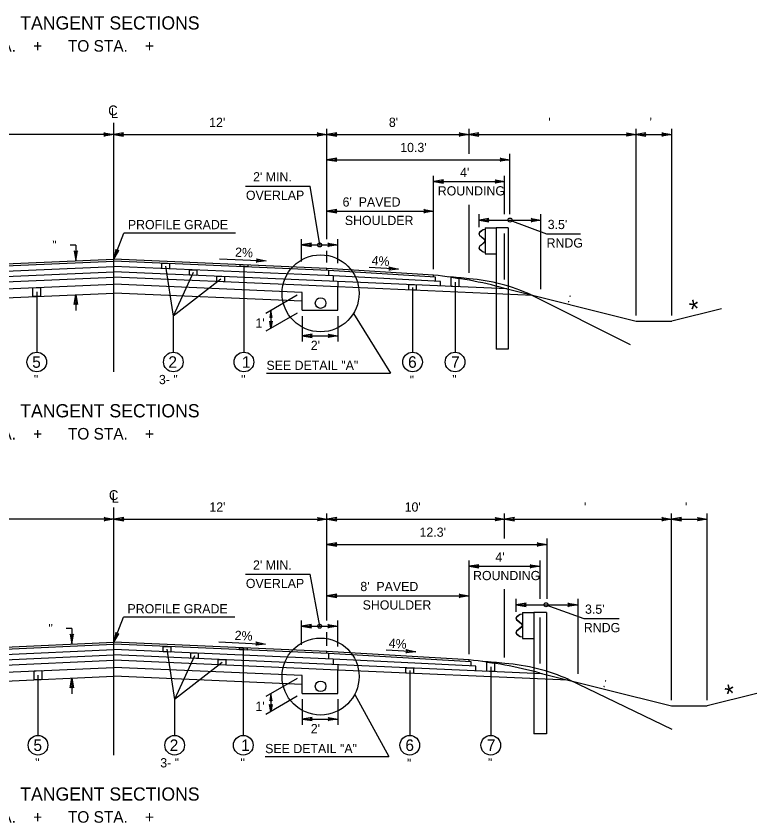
# Model space of a CAD drawing. Extents: x -592 to 1199, y -590 to 416.
# Drawn here: x 227.3 to 339.6, y 43.7 to 166.1 of the extents above; entities that cross this region are included whole.
import ezdxf

# ---------------------------------------------------------------- set-up
doc = ezdxf.new("R2010")
doc.units = 0
doc.layers.add('1', color=7, linetype='Continuous')
doc.layers.add('Des_ Drain_ Ftrs', color=7, linetype='Continuous')

msp = doc.modelspace()

# ---------------------------------------------------------------- linework, layer by layer
at = {"layer": '1'}
for p, q in [((242.09, 112.15), (242.09, 149.92)), ((242.09, 148.16), (209.76, 148.16)), ((242.09, 148.16), (274.42, 148.16)), ((274.42, 132.28), (274.42, 149.04)), ((274.42, 148.16), (295.97, 148.16)), ((295.97, 145.22), (295.97, 149.04)), ((295.97, 148.16), (321.31, 148.16)), ((321.31, 120.71), (321.31, 149.04)), ((321.31, 148.16), (326.69, 148.16)), ((326.69, 120.71), (326.69, 149.04)), ((302.17, 136.06), (302.17, 145.22)), ((274.42, 144.34), (302.17, 144.34)), ((290.58, 127.71), (290.58, 141.89)), ((290.61, 141.01), (301.39, 141.01)), ((301.36, 136.06), (301.36, 141.89)), ((262.09, 140.34), (271.86, 140.34)), ((273.32, 131.4), (271.86, 140.34)), ((295.97, 127.15), (295.97, 137.47)), ((274.42, 136.52), (290.58, 136.52)), ((297.48, 134.11), (297.48, 136.06)), ((306.86, 124.7), (306.86, 136.06)), ((297.48, 135.18), (306.86, 135.18)), ((302.17, 135.18), (307.73, 133.11)), ((298.08, 133.71), (297.56, 133.32)), ((298.09, 133.68), (297.58, 133.3)), ((298.39, 133.77), (298.08, 133.71)), ((298.39, 133.74), (298.09, 133.68)), ((298.39, 134), (298.39, 130.06)), ((298.39, 134), (300.08, 134)), ((300.08, 134), (300.08, 115.6)), ((301.9, 134), (300.08, 134)), ((301.9, 134), (301.9, 115.6)), ((242.09, 129.25), (243.61, 133.21)), ((260.53, 133.21), (243.61, 133.21)), ((270.58, 128.89), (270.58, 132.28)), ((276.06, 128.62), (276.06, 132.28)), ((297.54, 132.89), (298.28, 132.26)), ((297.56, 132.91), (298.3, 132.28)), ((301.36, 126.18), (301.36, 133.14)), ((307.73, 133.11), (312.88, 133.11)), ((236.34, 131.37), (235.46, 131.37)), ((236.34, 131.37), (236.34, 129)), ((270.58, 131.4), (276.06, 131.4)), ((298.28, 131.8), (297.54, 131.17)), ((298.3, 131.78), (297.56, 131.15)), ((298.36, 132.07), (298.36, 131.99)), ((298.39, 132.07), (298.39, 131.99)), ((274.42, 128.72), (274.42, 130.52)), ((297.56, 130.74), (298.08, 130.35)), ((297.58, 130.76), (298.09, 130.38)), ((298.08, 130.35), (298.39, 130.29)), ((298.09, 130.38), (298.39, 130.32)), ((298.39, 130.06), (300.08, 130.06)), ((209.52, 127.53), (242.09, 128.95)), ((209.76, 127.84), (242.09, 129.25)), ((274.42, 127.84), (242.09, 129.25)), ((274.66, 127.53), (242.09, 128.95)), ((258.1, 129.31), (265.19, 129)), ((182.49, 124.73), (242.09, 127.33)), ((208.82, 126.69), (242.09, 128.14)), ((275.37, 126.69), (242.09, 128.14)), ((301.7, 124.73), (242.09, 127.33)), ((249.95, 128.2), (251.12, 120.58)), ((261.83, 128.23), (261.83, 115.12)), ((274.42, 127.54), (274.42, 127.84)), ((290.58, 126.83), (274.42, 127.84)), ((274.66, 127.53), (274.66, 126.72)), ((290.89, 126.51), (274.66, 127.53)), ((285.29, 127.72), (280.8, 127.99)), ((213.6, 125.28), (242.09, 126.53)), ((270.58, 125.28), (242.09, 126.53)), ((254.13, 127.22), (251.12, 120.58)), ((258.3, 126.21), (251.12, 120.58)), ((275.36, 126.69), (275.36, 125.88)), ((291.61, 125.86), (275.36, 126.69)), ((290.58, 126.53), (290.58, 126.83)), ((290.89, 125.9), (290.89, 126.51)), ((213.5, 124.2), (242.09, 125.45)), ((270.68, 124.2), (242.09, 125.45)), ((276.07, 125.04), (270.58, 125.28)), ((276.07, 125.85), (276.07, 125.04)), ((276.07, 121.5), (276.07, 125.04)), ((305.62, 123.75), (276.07, 125.04)), ((287.39, 124.95), (287.39, 115.12)), ((291.61, 125.17), (291.61, 125.86)), ((293.84, 125.77), (293.84, 115.12)), ((297.48, 126.05), (297.48, 126.05)), ((213.5, 122.85), (242.09, 124.1)), ((230.41, 124.27), (230.41, 115.12)), ((236.34, 123.85), (236.34, 121.48)), ((270.68, 122.85), (242.09, 124.1)), ((269.92, 123.76), (265.16, 121.01)), ((270.68, 121.5), (270.68, 124.2)), ((270.68, 124.2), (270.68, 124.2)), ((301.36, 124.82), (321.31, 119.83)), ((305.36, 123.82), (320.41, 116.29)), ((265.92, 121.45), (265.9, 118.75)), ((270.68, 121.5), (276.07, 121.5)), ((334.23, 121.71), (326.69, 119.83)), ((334.23, 121.71), (326.69, 119.83)), ((251.12, 120.58), (251.12, 115.12)), ((269.92, 121.06), (265.14, 118.31)), ((270.68, 120.62), (270.68, 116.74)), ((276.07, 120.62), (276.07, 116.74)), ((278.44, 121.02), (284.03, 111.94)), ((321.31, 119.83), (326.69, 119.83)), ((270.68, 117.62), (276.07, 117.62)), ((301.9, 115.6), (300.08, 115.6)), ((265.24, 111.94), (284.03, 111.94)), ((242.09, 54.01), (242.09, 91.55)), ((274.42, 74.43), (274.42, 90.67)), ((301.36, 86.85), (301.36, 90.67)), ((326.68, 62.33), (326.68, 90.67)), ((332.07, 62.33), (332.07, 90.67)), ((242.11, 89.79), (209.78, 89.79)), ((242.11, 89.79), (274.44, 89.79)), ((274.44, 89.79), (301.39, 89.79)), ((301.39, 89.79), (326.68, 89.79)), ((326.68, 89.79), (332.07, 89.79)), ((274.42, 85.97), (307.79, 85.97)), ((307.79, 77.69), (307.79, 86.85)), ((295.97, 69.32), (295.97, 83.52)), ((306.75, 77.69), (306.75, 83.52)), ((295.96, 82.64), (306.74, 82.64)), ((262.09, 81.44), (271.86, 81.44)), ((273.32, 73.55), (271.86, 81.44)), ((301.36, 68.78), (301.36, 79.18)), ((274.42, 78.18), (295.97, 78.18)), ((303.1, 75.74), (303.1, 77.69)), ((312.49, 66.33), (312.49, 77.69)), ((303.1, 76.81), (312.49, 76.81)), ((307.62, 76.81), (313.38, 74.74)), ((242.09, 71.11), (243.55, 74.91)), ((260.47, 74.91), (243.55, 74.91)), ((303.72, 75.35), (303.18, 74.96)), ((303.73, 75.32), (303.2, 74.93)), ((304.05, 75.4), (303.72, 75.35)), ((304.05, 75.37), (303.73, 75.32)), ((304.05, 75.63), (304.05, 71.7)), ((304.05, 75.63), (305.8, 75.63)), ((305.8, 75.63), (305.8, 57.23)), ((307.69, 75.63), (305.8, 75.63)), ((306.75, 67.87), (306.75, 74.88)), ((307.69, 75.63), (307.69, 57.23)), ((313.38, 74.74), (318.73, 74.74)), ((270.57, 70.74), (270.57, 74.43)), ((270.57, 73.55), (276.06, 73.55)), ((276.06, 70.48), (276.06, 74.43)), ((303.17, 74.52), (303.93, 73.89)), ((303.19, 74.55), (303.95, 73.91)), ((304.02, 73.7), (304.02, 73.63)), ((304.05, 73.7), (304.05, 73.63)), ((235.75, 73.2), (234.87, 73.2)), ((235.75, 73.2), (235.75, 70.83)), ((274.42, 70.58), (274.42, 72.67)), ((303.93, 73.44), (303.17, 72.8)), ((303.18, 72.37), (303.72, 71.98)), ((303.95, 73.42), (303.19, 72.78)), ((303.2, 72.39), (303.73, 72.01)), ((209.75, 69.7), (242.09, 71.11)), ((274.42, 69.7), (242.09, 71.11)), ((258.04, 71.16), (265.12, 70.85)), ((303.72, 71.98), (304.05, 71.93)), ((303.73, 72.01), (304.05, 71.96)), ((304.05, 71.7), (305.8, 71.7)), ((208.81, 68.55), (242.09, 70)), ((209.52, 69.39), (242.09, 70.81)), ((274.66, 69.39), (242.09, 70.81)), ((275.36, 68.55), (242.09, 70)), ((250.15, 70.05), (251.32, 62.43)), ((261.73, 70.1), (261.73, 56.98)), ((287.88, 69.67), (283.39, 69.93)), ((177.11, 66.35), (242.09, 69.19)), ((307.07, 66.35), (242.09, 69.19)), ((254.33, 69.07), (251.32, 62.43)), ((274.42, 69.4), (274.42, 69.7)), ((295.97, 68.44), (274.42, 69.7)), ((274.66, 69.39), (274.66, 68.57)), ((296.27, 68.13), (274.66, 69.39)), ((275.36, 68.55), (275.36, 67.73)), ((297, 67.48), (275.36, 68.55)), ((213.6, 67.14), (242.09, 68.38)), ((270.58, 67.14), (242.09, 68.38)), ((258.51, 68.05), (251.32, 62.43)), ((276.06, 67.71), (276.06, 66.9)), ((295.97, 68.14), (295.97, 68.44)), ((296.27, 67.51), (296.27, 68.13)), ((297, 66.79), (297, 67.48)), ((299.25, 67.39), (299.25, 56.98)), ((303.1, 67.68), (303.1, 67.68)), ((213.5, 66.05), (242.09, 67.3)), ((230.6, 66.13), (230.6, 56.98)), ((270.68, 66.05), (242.09, 67.3)), ((276.06, 66.9), (270.58, 67.14)), ((276.06, 63.36), (276.06, 66.9)), ((311, 65.37), (276.06, 66.9)), ((276.06, 66.75), (276.06, 66.75)), ((286.97, 66.82), (286.97, 56.98)), ((306.75, 66.43), (326.68, 61.45)), ((213.5, 64.71), (242.09, 65.95)), ((235.75, 65.68), (235.75, 63.31)), ((270.68, 64.71), (242.09, 65.95)), ((269.91, 65.61), (265.16, 62.87)), ((270.68, 63.36), (270.68, 66.05)), ((270.68, 66.05), (270.68, 66.05)), ((311.1, 65.45), (326.72, 57.92)), ((269.91, 62.92), (265.14, 60.16)), ((265.92, 63.31), (265.9, 60.6)), ((270.68, 63.36), (276.06, 63.36)), ((270.68, 62.48), (270.68, 58.59)), ((276.06, 62.48), (276.06, 58.59)), ((278.63, 63.21), (283.82, 53.79)), ((339.61, 63.33), (332.07, 61.45)), ((251.32, 62.43), (251.32, 56.98)), ((326.68, 61.45), (332.07, 61.45)), ((270.68, 59.47), (276.06, 59.47)), ((307.69, 57.23), (305.8, 57.23)), ((265.04, 53.79), (283.82, 53.79))]:
    msp.add_line(p, q, dxfattribs=at)
for points in [[(249.38, 128.63), (250.53, 128.58), (250.53, 127.78), (249.38, 127.83)], [(253.55, 127.64), (254.7, 127.59), (254.7, 126.78), (253.55, 126.83)], [(261.26, 128.42), (262.4, 128.37), (262.4, 128.07), (261.26, 128.12)], [(257.73, 126.65), (258.88, 126.6), (258.88, 125.79), (257.73, 125.84)], [(293.27, 126.49), (294.42, 126.32), (294.42, 125.05), (293.27, 125.1)], [(229.83, 124.91), (230.98, 124.96), (230.98, 123.61), (229.83, 123.56)], [(286.81, 125.38), (287.96, 125.33), (287.96, 124.52), (286.81, 124.57)], [(249.58, 70.48), (250.73, 70.43), (250.73, 69.62), (249.58, 69.67)], [(261.15, 70.28), (262.3, 70.23), (262.3, 69.93), (261.15, 69.98)], [(253.76, 69.49), (254.9, 69.44), (254.9, 68.63), (253.76, 68.68)], [(257.93, 68.5), (259.08, 68.45), (259.08, 67.64), (257.93, 67.69)], [(298.68, 68.11), (299.82, 67.93), (299.82, 66.67), (298.68, 66.72)], [(230.03, 66.78), (231.17, 66.83), (231.17, 65.48), (230.03, 65.43)], [(286.4, 67.26), (287.55, 67.21), (287.55, 66.4), (286.4, 66.45)]]:
    msp.add_lwpolyline(points, close=True, dxfattribs=at)
for centre, radius in [((302.17, 135.18), 0.3), ((273.32, 131.4), 0.3), ((273.45, 124.06), 5.84), ((273.45, 122.58), 0.808), ((230.41, 113.64), 1.49), ((251.12, 113.64), 1.49), ((261.83, 113.64), 1.49), ((287.39, 113.64), 1.49), ((293.84, 113.64), 1.49), ((273.32, 73.55), 0.3), ((273.45, 65.92), 5.84), ((273.45, 64.43), 0.808), ((230.6, 55.49), 1.49), ((251.32, 55.49), 1.49), ((261.73, 55.49), 1.49), ((286.97, 55.49), 1.49), ((299.25, 55.49), 1.49)]:
    msp.add_circle(centre, radius, dxfattribs=at)
for centre, radius, start, end in [((297.73, 133.1), 0.278, 126.9799, 229.021), ((297.73, 133.1), 0.249, 126.9799, 229.021), ((298.11, 132.07), 0.249, 0, 49.0365), ((298.11, 132.07), 0.278, 0, 49.0365), ((297.73, 130.96), 0.278, 130.979, 233.0201), ((297.73, 130.96), 0.249, 130.979, 233.0201), ((298.11, 131.99), 0.249, 310.9635, 0), ((298.11, 131.99), 0.278, 310.9635, 0), ((283.7, 59.99), 67.19, 74.7619, 84.1205), ((285.16, 25.61), 101.24, 83.8633, 85.6775), ((293.86, 98.98), 27.37, 65.1374, 85.5513), ((289.08, 1.61), 67.19, 74.7598, 84.1183)]:
    msp.add_arc(centre, radius, start, end, dxfattribs=at)
msp.add_ellipse((307.62, 76.81), major_axis=(-0.311, 0), ratio=0.964041, dxfattribs=at)
for centre, major_axis, start_param, end_param in [((303.36, 74.73), (-0.288, 0), 5.35781, 7.138763), ((303.36, 74.73), (-0.258, 0), 5.35781, 7.138763), ((303.76, 73.7), (0.258, 0), 0, 0.855848), ((303.76, 73.63), (0.258, 0), 5.427337, 6.283185), ((303.76, 73.7), (0.288, 0), 0, 0.855848), ((303.76, 73.63), (0.288, 0), 5.427337, 6.283185), ((303.36, 72.59), (-0.288, 0), 5.427608, 7.208561), ((303.36, 72.59), (-0.258, 0), 5.427608, 7.208561), ((290.14, -32.76), (105.02, 0), 1.463691, 1.495354), ((299.17, 40.62), (28.39, 0), 1.136862, 1.493152)]:
    msp.add_ellipse(centre, major_axis=major_axis, ratio=0.964041, start_param=start_param, end_param=end_param, dxfattribs=at)
at = {"layer": 'Des_ Drain_ Ftrs'}
for points in [[(242.09, 148.16), (240.6, 147.91), (240.9, 148.16), (240.6, 148.41)], [(242.09, 148.16), (243.58, 147.91), (243.28, 148.16), (243.58, 148.41)], [(274.42, 148.16), (272.93, 147.91), (273.23, 148.16), (272.93, 148.41)], [(274.42, 148.16), (275.91, 147.91), (275.61, 148.16), (275.91, 148.41)], [(295.97, 148.16), (294.48, 147.91), (294.78, 148.16), (294.48, 148.41)], [(295.97, 148.16), (297.46, 147.91), (297.17, 148.16), (297.46, 148.41)], [(321.31, 148.16), (319.82, 147.91), (320.11, 148.16), (319.82, 148.41)], [(321.31, 148.16), (322.79, 147.91), (322.5, 148.16), (322.79, 148.41)], [(326.69, 148.16), (325.21, 147.91), (325.5, 148.16), (325.21, 148.41)], [(274.42, 144.34), (275.91, 144.09), (275.61, 144.34), (275.91, 144.58)], [(302.17, 144.34), (300.68, 144.09), (300.98, 144.34), (300.68, 144.58)], [(290.61, 141.01), (292.1, 140.76), (291.81, 141.01), (292.1, 141.26)], [(301.39, 141.01), (299.9, 140.76), (300.2, 141.01), (299.9, 141.26)], [(274.42, 136.52), (275.91, 136.27), (275.61, 136.52), (275.91, 136.77)], [(290.58, 136.52), (289.09, 136.27), (289.39, 136.52), (289.09, 136.77)], [(297.48, 135.18), (298.97, 134.93), (298.67, 135.18), (298.97, 135.43)], [(306.86, 135.18), (305.37, 134.93), (305.67, 135.18), (305.37, 135.43)], [(270.58, 131.4), (272.06, 131.15), (271.77, 131.4), (272.06, 131.65)], [(276.06, 131.4), (274.57, 131.15), (274.87, 131.4), (274.57, 131.65)], [(236.34, 129), (236.59, 130.49), (236.34, 130.2), (236.1, 130.49)], [(242.09, 129.25), (242.85, 130.55), (242.52, 130.37), (242.39, 130.73)], [(265.19, 129), (263.69, 128.81), (264, 129.05), (263.71, 129.31)], [(285.29, 127.72), (283.79, 127.56), (284.1, 127.79), (283.82, 128.06)], [(236.34, 123.85), (236.59, 122.36), (236.34, 122.66), (236.1, 122.36)], [(265.92, 121.45), (265.73, 120.37), (265.91, 120.58), (266.09, 120.37)], [(265.9, 118.75), (265.73, 119.83), (265.91, 119.62), (266.09, 119.83)], [(270.68, 117.62), (272.17, 117.37), (271.87, 117.62), (272.17, 117.87)], [(276.07, 117.62), (274.58, 117.37), (274.87, 117.62), (274.58, 117.87)], [(242.11, 89.79), (240.63, 89.54), (240.92, 89.79), (240.63, 90.04)], [(242.11, 89.79), (243.6, 89.54), (243.31, 89.79), (243.6, 90.04)], [(274.44, 89.79), (272.96, 89.54), (273.25, 89.79), (272.96, 90.04)], [(274.44, 89.79), (275.93, 89.54), (275.64, 89.79), (275.93, 90.04)], [(301.39, 89.79), (299.9, 89.54), (300.19, 89.79), (299.9, 90.04)], [(301.39, 89.79), (302.87, 89.54), (302.58, 89.79), (302.87, 90.04)], [(326.68, 89.79), (325.19, 89.54), (325.49, 89.79), (325.19, 90.04)], [(326.68, 89.79), (328.17, 89.54), (327.88, 89.79), (328.17, 90.04)], [(332.07, 89.79), (330.58, 89.54), (330.88, 89.79), (330.58, 90.04)], [(274.42, 85.97), (275.91, 85.72), (275.62, 85.97), (275.91, 86.22)], [(307.79, 85.97), (306.3, 85.72), (306.6, 85.97), (306.3, 86.22)], [(295.96, 82.64), (297.45, 82.4), (297.15, 82.64), (297.45, 82.89)], [(306.74, 82.64), (305.25, 82.4), (305.54, 82.64), (305.25, 82.89)], [(274.42, 78.18), (275.91, 77.93), (275.61, 78.18), (275.91, 78.43)], [(295.97, 78.18), (294.48, 77.93), (294.78, 78.18), (294.48, 78.43)], [(303.1, 76.81), (304.64, 76.56), (304.34, 76.81), (304.64, 77.06)], [(312.49, 76.81), (310.94, 76.56), (311.25, 76.81), (310.94, 77.06)], [(270.57, 73.55), (272.06, 73.3), (271.77, 73.55), (272.06, 73.8)], [(276.06, 73.55), (274.57, 73.3), (274.87, 73.55), (274.57, 73.8)], [(235.75, 70.83), (236, 72.32), (235.75, 72.03), (235.5, 72.32)], [(242.09, 71.11), (242.85, 72.41), (242.51, 72.22), (242.39, 72.59)], [(265.12, 70.85), (263.63, 70.67), (263.93, 70.9), (263.65, 71.16)], [(287.88, 69.67), (286.38, 69.5), (286.69, 69.73), (286.41, 70)], [(235.75, 65.68), (236, 64.19), (235.75, 64.49), (235.5, 64.19)], [(265.92, 63.31), (265.73, 62.22), (265.91, 62.44), (266.09, 62.22)], [(265.9, 60.6), (265.72, 61.69), (265.9, 61.47), (266.09, 61.68)], [(270.68, 59.47), (272.16, 59.23), (271.87, 59.47), (272.16, 59.72)], [(276.06, 59.47), (274.58, 59.23), (274.87, 59.47), (274.58, 59.72)]]:
    msp.add_lwpolyline(points, close=True, dxfattribs=at)

# ---------------------------------------------------------------- texts
at = {"layer": '1'}
for s, height, p in [('TANGENT SECTIONS', 2, (227.91, 164.09)), ('STA.    +      TO STA.    +     ', 1.75, (222.06, 160.73)), ("12'", 1.4, (256.56, 149.31)), ("8'", 1.4, (283.81, 149.31)), ("  '", 1.4, (306.94, 149.31)), (" '", 1.4, (322.81, 149.31)), ("10.3'", 1.4, (285.53, 145.49)), ("2' MIN.", 1.4, (263.22, 141.04)), ("4'", 1.4, (294.61, 141.71)), ('OVERLAP', 1.4, (262.13, 138.24)), ('ROUNDING', 1.4, (291.22, 138.91)), ("6'  PAVED", 1.4, (276.79, 137.22)), ('PROFILE GRADE', 1.4, (244.23, 133.79)), ('SHOULDER', 1.4, (277.13, 134.42)), ("3.5'", 1.4, (307.89, 133.81)), ('RNDG', 1.4, (307.72, 131.01)), ("2'", 1.4, (271.97, 115.47)), ('5', 1.75, (229.72, 112.76)), ('2', 1.75, (250.37, 112.76)), ('1', 1.75, (261.53, 112.76)), ('SEE DETAIL "A"', 1.4, (265.25, 112.44)), ('6', 1.75, (286.72, 112.76)), ('7', 1.75, (293.25, 112.76)), (' "', 1.4, (229.46, 110.28)), ('3- "', 1.4, (248.94, 110.28)), (' "', 1.4, (260.89, 110.28)), (' "', 1.4, (286.44, 110.18)), (' "', 1.4, (292.9, 110.28)), ('TANGENT SECTIONS', 2, (227.91, 105.24)), ('STA.    +      TO STA.    +     ', 1.75, (222.06, 101.88)), ("12'", 1.4, (256.59, 90.94)), ("10'", 1.4, (286.2, 90.94)), ("  '", 1.4, (312.34, 90.94)), (" '", 1.4, (328.18, 90.94)), ("12.3'", 1.4, (288.46, 87.12)), ("4'", 1.4, (299.96, 83.34)), ("2' MIN.", 1.4, (263.21, 82.14)), ('ROUNDING', 1.4, (296.57, 80.54)), ('OVERLAP', 1.4, (262.12, 79.34)), ("8'  PAVED", 1.4, (279.48, 78.88)), ('SHOULDER', 1.4, (279.83, 76.08)), ('PROFILE GRADE', 1.4, (244.17, 75.5)), ("3.5'", 1.4, (313.55, 75.44)), ('RNDG', 1.4, (313.37, 72.64)), ("2'", 1.4, (271.97, 57.32)), ('5', 1.75, (229.91, 54.62)), ('2', 1.75, (250.57, 54.62)), ('1', 1.75, (261.42, 54.62)), ('6', 1.75, (286.31, 54.62)), ('7', 1.75, (298.66, 54.62)), ('SEE DETAIL "A"', 1.4, (265.05, 54.29)), (' "', 1.4, (229.66, 52.13)), ('3- "', 1.4, (249.14, 52.13)), (' "', 1.4, (260.78, 52.13)), (' "', 1.4, (286.03, 52.04)), (' "', 1.4, (298.31, 52.13)), ('TANGENT SECTIONS', 2, (227.91, 47.09)), ('STA.    +      TO STA.    +     ', 1.75, (222.06, 43.74))]:
    msp.add_text(s, height=height, dxfattribs=at).set_placement(p)
for s, height, rotation, p in [('  "', 1.4, 0.1438, (231.73, 130.67)), ('2%', 1.4, 357.3732, (260.46, 129.62)), ('4%', 1.4, 356.3472, (281.16, 128.36)), (' : ', 1.4, 345.7718, (310.28, 122.88)), ('*', 2.8, 12.8479, (329.79, 120.18)), ("1'", 1.4, 0.1438, (263.57, 118.84)), ('  "', 1.4, 0.1438, (231.14, 72.5)), ('2%', 1.4, 357.3731, (260.4, 71.48)), ('4%', 1.4, 356.3924, (283.75, 70.3)), (' : ', 1.4, 345.7718, (315.66, 64.5)), ('*', 2.8, 12.8479, (335.16, 61.8)), ("1'", 1.4, 0.1438, (263.57, 60.69))]:
    msp.add_text(s, height=height, rotation=rotation, dxfattribs=at).set_placement(p)
at = {"layer": 'Des_ Drain_ Ftrs'}
for s, p in [('C', (241.24, 151.06)), ('L', (241.64, 150.66)), ('C', (241.35, 92.69)), ('L', (241.75, 92.29))]:
    msp.add_text(s, height=1.5, dxfattribs=at).set_placement(p)

doc.saveas('drawing.dxf')
